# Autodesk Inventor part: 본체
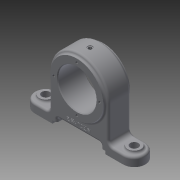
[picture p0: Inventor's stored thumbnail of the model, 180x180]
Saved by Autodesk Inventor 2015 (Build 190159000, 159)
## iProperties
Created: 2019-05
Part Number: 본체
Material: 알루미늄 6061
Document SubType Name: Modeling
Designer: now
Density: 2.7 g/cm^3
Appearance: 기본값
Mass: 454.985 g
Surface Area: 318.799 cm^2
Volume: 168.513 cm^3
Author: now
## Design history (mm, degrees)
sketch "스케치1"
  geometry: L1 (-75, 0)-(75, 0); L2 (-60, 15)-(60, 15); L3 (60, -15)-(-60, -15); A1 r 15 centre (-60, 0) between (-60, 15) and (-60, -15); A2 r 15 centre (60, 0) between (60, -15) and (60, 15); 2 further points
  constraints: 8 end point, 6 point on circle, 4 tangent, 2 centre point, 2 point on line, 1 coincident, 1 horizontal, 1 midpoint, 1 parallel
  dimensions: "d0" = 120 distance of A2.centre A1.centre; "d2" = 15 radius of A2
extrude "돌출1" new body sketch "스케치1" distance "d3" = 12; taper "d4" = 0 deg
sketch "스케치2"
  geometry: L1 (75, 12)-(75, 0) reference; L2 (75, 0)-(-75, 0) reference; L3 (-75, 0)-(-75, 12) reference; L4 (-75, 12)-(75, 12) reference; C1 r 40 at (0, 60); 2 further points
  constraints: 1 centre point, 1 midpoint, 1 vertical alignment
  dimensions: "d5" = 80 diameter of C1; "d6" = 60 distance of point (0, 0) C1.centre
extrude "돌출2" join sketch "스케치2" stored distance "d7" = 30; taper "d8" = 0 deg
sketch "스케치3"
  geometry: C1 r 40 at (0, 0) reference; C2 r 36 at (0, 0); 1 further point
  constraints: 1 centre point, 1 coincident
  dimensions: "d9" = 72 diameter of C2
extrude "돌출3" join sketch "스케치3" distance "d10" = 3; taper "d11" = 0 deg
sketch "스케치4"
  geometry: C1 r 40 at (0, 0) reference; C2 r 36 at (0, 0); 1 further point
  constraints: 1 centre point, 1 coincident
  dimensions: "d12" = 72 diameter of C2
extrude "돌출4" join sketch "스케치4" distance "d13" = 3; taper "d14" = 0 deg
node "작업 평면1"
sketch "스케치5"
  geometry: L1 (36, -15)-(36, -18) reference; L2 (36, -18)-(-36, -18) reference; L3 (-36, -18)-(-36, -15) reference; L4 (-36, -15)-(-40, -15) reference; L5 (-40, -15)-(-40, 15) reference; L6 (-40, 15)-(-36, 15) reference; L7 (-36, 15)-(-36, 18) reference; L8 (-36, 18)-(36, 18) reference; L9 (36, 18)-(36, 15) reference; L10 (36, 15)-(40, 15) reference; L11 (40, 15)-(40, -15) reference; L12 (40, -15)-(36, -15) reference; L13 (-40, 15)-(40, 15); L14 (40, 15)-(40, -15); L15 (40, -15)-(-40, -15); L16 (-40, -15)-(-40, 15); L17 (-40, 15)-(40, -15); L18 (40, 15)-(-40, -15); 1 further point
  constraints: 12 end point, 2 midpoint, 2 parallel, 1 horizontal, 1 perpendicular
  dimensions: "d16" = 80 distance of L13.start L13.end; "d17" = 30 distance between parallel lines of L13 L15
extrude "돌출5" join sketch "스케치5" stored distance "d18" = 3; taper "d19" = 0 deg
sketch "스케치6"
  geometry: C1 r 9 at (60, 0); A1 r 15 centre (60, 0) between (60, -15) and (60, 15) reference; 1 further point
  constraints: 1 centre point, 1 coincident
  dimensions: "d20" = 18 diameter of C1
extrude "돌출6" join sketch "스케치6" distance "d21" = 3; taper "d22" = 0 deg
hole "구멍1" diameter "d25" = 11; stored, may be unused: countersink angle "d29" = 90 deg, drill point angle "d31" = 118 deg; dims "d23" = 10, "d24" = 10, "d26" = 6, "d27" = 4, "d28" = 2, "d30" = 8
sketch "스케치7"
  geometry: L1 (69, 15)-(69, 12) reference; L2 (69, 12)-(75, 12) reference; L3 (75, 12)-(75, 0) reference; L4 (75, 0)-(65.5, 0) reference; L5 (65.5, 0)-(65.5, 15) reference; L6 (65.5, 15)-(69, 15) reference; L7 (-40, 12)-(-40, 60) reference; L8 (40, 60)-(40, 12) reference; L9 (40, 12)-(51, 12) reference; L10 (51, 12)-(51, 15) reference; L11 (51, 15)-(54.5, 15) reference; L12 (54.5, 15)-(54.5, 0) reference; L13 (54.5, 0)-(-54.5, 0) reference; L14 (-54.5, 0)-(-54.5, 15) reference; L15 (-54.5, 15)-(-51, 15) reference; L16 (-51, 15)-(-51, 12) reference; L17 (-51, 12)-(-40, 12) reference; L18 (-75, 0)-(-75, 12) reference; L19 (-75, 12)-(-69, 12) reference; L20 (-69, 12)-(-69, 15) reference; L21 (-69, 15)-(-65.5, 15) reference; L22 (-65.5, 15)-(-65.5, 0) reference; L23 (-65.5, 0)-(-75, 0) reference; L24 (36, 0)-(-36, 0); L25 (-36, 0)-(-36, 4); L26 (-36, 4)-(36, 4); L27 (36, 4)-(36, 0); L28 (36, 0)-(-36, 4); L29 (-36, 0)-(36, 4); A1 r 40 centre (0, 60) between (40, 60) and (-40, 60) reference; 3 further points
  constraints: 12 end point, 4 midpoint, 2 parallel, 1 horizontal, 1 perpendicular
  dimensions: "d32" = 4 distance between parallel lines of L26 L13; "d33" = 72 distance between parallel lines of L25 L27
extrude "돌출7" cut sketch "스케치7" stored distance "d34" = 3; taper "d35" = 0 deg
sketch "스케치8"
  geometry: L1 (-90, -10)-(-30, -10); L2 (-30, -10)-(-30, 10); L3 (-30, 10)-(-90, 10); L4 (-90, 10)-(-90, -10); L5 (-90, -10)-(-30, 10); L6 (-30, -10)-(-90, 10); 1 further point
  constraints: 12 end point, 2 midpoint, 2 parallel, 1 horizontal, 1 perpendicular
  dimensions: "d36" = 10 distance from line of L3 point (-60, 0); "d37" = 60 distance of L1.start L1.end
extrude "돌출8" cut sketch "스케치8" stored distance "d38" = 0; taper "d39" = 0 deg
node "작업 평면2"
sketch "스케치9"
  geometry: C1 r 3.5 at (0, 0); 1 further point
  constraints: 1 centre point, 1 coincident
  dimensions: "d41" = 7 diameter of C1
extrude "돌출9" cut sketch "스케치9" distance "d42" = 1; taper "d43" = 0 deg
sketch "스케치10"
  geometry: L1 (8.888, -15)-(-8.888, -15) reference; L2 (-8.888, -15)-(-8.888, 15) reference; L3 (-8.888, 15)-(8.888, 15) reference; L4 (8.888, 15)-(8.888, -15) reference; C1 r 3.5 at (0, 0) reference; C2 r 3.5 at (0, 0) reference
hole "구멍2" sketch "스케치10" at (0, 0) diameter "d44" = 4.917; stored, may be unused: countersink angle "d48" = 90 deg, drill point angle "d50" = 118 deg; dims "d45" = 8, "d46" = 6, "d47" = 2, "d49" = 10
sketch "스케치11"
  geometry: C1 r 36 at (0, 0) reference; C2 r 26 at (0, 0); 1 further point
  constraints: 1 centre point, 1 coincident
  dimensions: "d51" = 52 diameter of C2
extrude "돌출10" cut sketch "스케치11" stored distance "d52" = 1; taper "d53" = 0 deg
sketch "스케치12"
  geometry: C1 r 26 at (0, 0) reference; 2 further points
  constraints: 1 vertical alignment
  dimensions: "d54" = 31 distance of point (0, 31) C1.centre
hole "구멍3" sketch "스케치12" at (0, 31) diameter "d55" = 3.242; stored, may be unused: countersink angle "d59" = 90 deg, drill point angle "d61" = 118 deg; dims "d56" = 6, "d57" = 6, "d58" = 2, "d60" = 8
sketch "스케치13"
  geometry: C1 r 1.5 at (0, 26); 2 further points
  constraints: 2 vertical alignment, 1 centre point, 1 other
  dimensions: "d65" = 3 diameter of C1
extrude "돌출11" cut sketch "스케치13" stored distance "d66" = 1; taper "d67" = 0 deg
fillet "모깎기1" dims "d68" = 6
sketch "스케치14"
  geometry: 1 further point
hole "구멍4" sketch "스케치14" at (0, 0) diameter "d69" = 2; stored, may be unused: countersink angle "d73" = 90 deg, drill point angle "d75" = 118 deg; dims "d70" = 6, "d71" = 6, "d72" = 2, "d74" = 30
chamfer "모따기1" distance "d76" = 1; stored, may be unused: second distance "d77" = 2, angle "d78" = 45 deg
fillet "모깎기4" dims "d81" = 3
fillet "모깎기5" dims "d82" = 3
fillet "모깎기6" dims "d83" = 3
fillet "모깎기7" dims "d84" = 3
sketch "스케치15"
  geometry: L1 (33, 10)-(87, 10) reference; 2 further points
  constraints: 1 vertical alignment, 1 other
  dimensions: "d85" = 7 distance from line of L1 point (60, 17)
feature "엠보싱1" sketch "스케치15" dims "d0" = 120, "d2" = 15, "d86" = 0.5, "d87" = 0
node "솔리드1"
mirror "대칭1"
pattern_circular "원형 패턴1" dims angle "d63" = 360 deg
mirror "대칭2"
node "절단 모서리 투영1"
node "절단 모서리 투영2"
node "절단 모서리 투영3"
node "절단 모서리 투영4"
